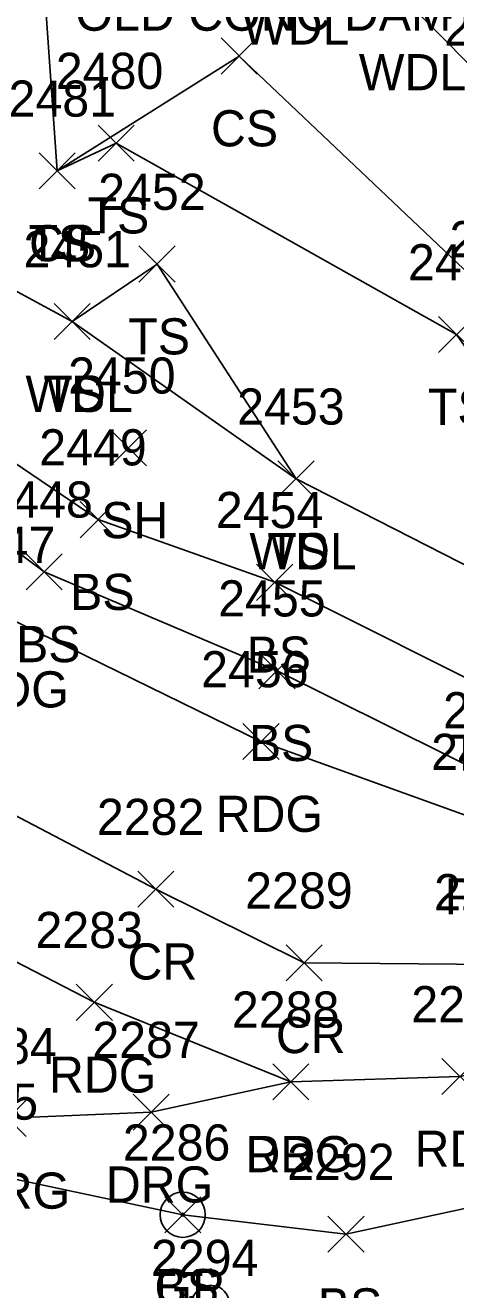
# Model space of a CAD drawing. Extents: x 1512665 to 1513714, y 110636 to 112816.
# Drawn here: x 1512998.3 to 1513022.1, y 110740.2 to 110810.2 of the extents above; entities that cross this region are included whole.
import ezdxf

# ---------------------------------------------------------------- set-up
doc = ezdxf.new("R2010")
doc.units = 0
for name, color, linetype in [('C_C', 7, 'Continuous'), ('L_A', 7, 'Continuous'), ('L_C', 7, 'Continuous'), ('L_I', 7, 'Continuous'), ('L_TIC', 7, 'Continuous'), ('LAWA', 7, 'Continuous'), ('LELB', 7, 'Continuous'), ('LTD', 7, 'Continuous'), ('P_A', 7, 'Continuous'), ('P_I', 7, 'Continuous'), ('P_TIC', 7, 'Continuous'), ('PEU', 7, 'Continuous'), ('PRC', 7, 'Continuous'), ('R_A', 7, 'Continuous'), ('R_I', 7, 'Continuous'), ('R_TIC', 7, 'Continuous'), ('RDG', 7, 'Continuous'), ('RGP', 7, 'Continuous')]:
    doc.layers.add(name, color=color, linetype=linetype)

msp = doc.modelspace()

# ---------------------------------------------------------------- linework, layer by layer
at = {"layer": 'L_TIC'}
for points in [[(1513009.115, 110807.489), (1513011.115, 110809.489)], [(1513011.115, 110807.489), (1513009.115, 110809.489)], [(1513002.312, 110802.67), (1513004.312, 110804.67)], [(1513004.312, 110802.67), (1513002.312, 110804.67)], [(1512999.042, 110801.133), (1513001.042, 110803.133)], [(1513001.042, 110801.133), (1512999.042, 110803.133)], [(1512999.042, 110801.133), (1513001.042, 110803.133)], [(1513001.042, 110801.133), (1512999.042, 110803.133)], [(1513004.569, 110795.978), (1513006.569, 110797.978)], [(1513006.569, 110795.978), (1513004.569, 110797.978)], [(1512999.869, 110792.798), (1513001.869, 110794.798)], [(1513001.869, 110792.798), (1512999.869, 110794.798)], [(1512999.869, 110792.798), (1513001.869, 110794.798)], [(1513001.869, 110792.798), (1512999.869, 110794.798)], [(1513021.152, 110792.076), (1513023.152, 110794.076)], [(1513023.152, 110792.076), (1513021.152, 110794.076)], [(1513002.992, 110785.812), (1513004.992, 110787.812)], [(1513004.992, 110785.812), (1513002.992, 110787.812)], [(1513012.264, 110784.095), (1513014.264, 110786.095)], [(1513014.264, 110784.095), (1513012.264, 110786.095)], [(1513012.264, 110784.095), (1513014.264, 110786.095)], [(1513014.264, 110784.095), (1513012.264, 110786.095)], [(1513001.316, 110781.838), (1513003.316, 110783.838)], [(1513003.316, 110781.838), (1513001.316, 110783.838)], [(1512998.323, 110778.951), (1513000.323, 110780.951)], [(1513000.323, 110778.951), (1512998.323, 110780.951)], [(1513011.084, 110778.37), (1513013.084, 110780.37)], [(1513013.084, 110778.37), (1513011.084, 110780.37)], [(1513011.212, 110773.48), (1513013.212, 110775.48)], [(1513013.212, 110773.48), (1513011.212, 110775.48)], [(1513005.992, 110743.376), (1513007.992, 110745.376)], [(1513007.992, 110743.376), (1513005.992, 110745.376)], [(1513015.029, 110742.308), (1513017.029, 110744.308)], [(1513017.029, 110742.308), (1513015.029, 110744.308)]]:
    msp.add_lwpolyline(points, dxfattribs=at)
at = {"layer": 'LAWA'}
msp.add_lwpolyline([(1512988.199, 110800.659), (1513000.869, 110793.798), (1513013.264, 110785.095), (1513028.637, 110777.265), (1513031.778, 110776.166), (1513035.849, 110774.486), (1513038.334, 110774.274), (1513040.786, 110775.756), (1513040.029, 110778.791), (1513034.839, 110783.794), (1513031.373, 110791.45), (1513032.455, 110794.874), (1513030.687, 110802.22), (1513024.783, 110806.061), (1513019.321, 110811.594), (1513012.859, 110814.122), (1513012.233, 110818.887), (1513011.96, 110820.134), (1513029.824, 110821.619), (1513035.802, 110824.023), (1513038.307, 110832.035), (1513040.001, 110853.344)], dxfattribs=at)
at = {"layer": 'LELB'}
for points in [[(1513042.977, 110772.935), (1513038.334, 110774.274), (1513035.486, 110779.791), (1513033.224, 110783.595), (1513025.018, 110794.357), (1513010.115, 110808.489), (1513000.042, 110802.133), (1512999.104, 110815.556), (1513001.845, 110823.582), (1513003.953, 110835.587)], [(1512965.768, 110809.049), (1512985.021, 110794.556), (1513002.316, 110782.838), (1513012.084, 110779.37), (1513025.948, 110772.452), (1513031.778, 110776.166)], [(1512964.105, 110806.986), (1512983.29, 110791.889), (1512999.323, 110779.951), (1513012.212, 110774.48), (1513024.663, 110768.294), (1513032.242, 110771.906), (1513035.849, 110774.486)], [(1513035.486, 110779.791), (1513029.907, 110781.961), (1513022.152, 110793.076), (1513003.312, 110803.67), (1513000.042, 110802.133)], [(1513000.869, 110793.798), (1513005.569, 110796.978), (1513013.264, 110785.095)], [(1512958.132, 110793.433), (1512973.652, 110777.453), (1512981.607, 110755.641), (1512996.294, 110746.637), (1513006.992, 110744.376), (1513016.029, 110743.308), (1513026.953, 110745.673), (1513036.177, 110748.289)]]:
    msp.add_lwpolyline(points, dxfattribs=at)
at = {"layer": 'LTD'}
msp.add_arc((1513008.539, 110739.425), 1.047, 335.52715, 180.95627, dxfattribs=at)
at = {"layer": 'P_TIC'}
for points in [[(1513010.324, 110769.561), (1513012.324, 110771.561)], [(1513012.324, 110769.561), (1513010.324, 110771.561)], [(1513004.499, 110761.392), (1513006.499, 110763.392)], [(1513006.499, 110761.392), (1513004.499, 110763.392)], [(1513012.716, 110757.318), (1513014.716, 110759.318)], [(1513014.716, 110757.318), (1513012.716, 110759.318)], [(1513001.098, 110755.133), (1513003.098, 110757.133)], [(1513003.098, 110755.133), (1513001.098, 110757.133)], [(1513011.974, 110750.731), (1513013.974, 110752.731)], [(1513013.974, 110750.731), (1513011.974, 110752.731)], [(1513021.336, 110751.03), (1513023.336, 110753.03)], [(1513023.336, 110751.03), (1513021.336, 110753.03)]]:
    msp.add_lwpolyline(points, dxfattribs=at)
at = {"layer": 'PEU'}
for points in [[(1512701.918, 111049.687), (1512700.272, 111027.695), (1512701.575, 110993.777), (1512707.634, 110973.739), (1512708.973, 110956.468), (1512713.567, 110946.899), (1512719.219, 110936.541), (1512726.895, 110929.376), (1512741.614, 110919.596), (1512758.159, 110912.379), (1512787.354, 110896.005), (1512813.053, 110887.984), (1512838.367, 110874.777), (1512855.917, 110864.835), (1512882.817, 110848.349), (1512898.24, 110841.366), (1512913.486, 110833.402), (1512927.92, 110827.382), (1512944.462, 110817.212), (1512962.879, 110803.833), (1512982.126, 110789.052), (1512997.253, 110777.445), (1513011.324, 110770.561), (1513024.004, 110765.991)], [(1512908.545, 110823.763), (1512922.462, 110816.848), (1512937.29, 110809.107), (1512956.028, 110794.571), (1512958.132, 110793.433), (1512975.798, 110779.469), (1512988.794, 110763.009), (1513002.098, 110756.133), (1513012.974, 110751.731), (1513022.336, 110752.03), (1513042.715, 110756.056), (1513045.977, 110758.546), (1513043.773, 110764.486), (1513041.72, 110768.766), (1513036.521, 110767.718), (1513024.004, 110765.991)]]:
    msp.add_lwpolyline(points, dxfattribs=at)
at = {"layer": 'PRC'}
msp.add_lwpolyline([(1512910.919, 110828.697), (1512924.695, 110822.052), (1512939.408, 110813.161), (1512959.787, 110799.435), (1512979.162, 110782.894), (1512994.968, 110767.907), (1513005.499, 110762.392), (1513013.716, 110758.318), (1513024.25, 110758.228), (1513034.128, 110760.688), (1513043.773, 110764.486)], dxfattribs=at)
at = {"layer": 'R_TIC'}
for points in [[(1513011.974, 110750.731), (1513013.974, 110752.731)], [(1513013.974, 110750.731), (1513011.974, 110752.731)], [(1513004.245, 110749.054), (1513006.245, 110751.054)], [(1513006.245, 110749.054), (1513004.245, 110751.054)], [(1512996.328, 110748.713), (1512998.328, 110750.713)], [(1512998.328, 110748.713), (1512996.328, 110750.713)]]:
    msp.add_lwpolyline(points, dxfattribs=at)
at = {"layer": 'RDG'}
msp.add_lwpolyline([(1512988.794, 110763.009), (1512997.328, 110749.713), (1513005.245, 110750.054), (1513012.974, 110751.731)], dxfattribs=at)
at = {"layer": 'RGP'}
msp.add_line((1513006.992, 110744.376), (1513006.992, 110744.376), dxfattribs=at)
for radius in [1.25, 0.0833]:
    msp.add_circle((1513006.992, 110744.376), radius, dxfattribs=at)

# ---------------------------------------------------------------- texts
at = {"layer": 'C_C'}
msp.add_text('TIE=25.02', height=2, dxfattribs=at).set_placement((1513021.817, 110768.939))
at = {"layer": 'L_A'}
for s, p in [('WDL', (1513010.276, 110809.122)), ('WDL', (1513016.738, 110806.594)), ('CS', (1513008.556, 110803.489)), ('TS', (1513001.721, 110798.67)), ('TS', (1512998.452, 110797.133)), ('CS', (1512998.483, 110797.133)), ('TS', (1513003.979, 110791.978)), ('TS', (1512999.278, 110788.798)), ('WDL', (1512998.286, 110788.798)), ('TS', (1513020.561, 110788.076)), ('SH', (1513002.48, 110781.812)), ('WDL', (1513010.681, 110780.095)), ('TS', (1513011.673, 110780.095)), ('BS', (1513000.757, 110777.838)), ('BS', (1512997.764, 110774.951)), ('BS', (1513010.525, 110774.37)), ('BS', (1513010.653, 110769.48)), ('BS', (1513005.433, 110739.376)), ('BS', (1513014.47, 110738.308))]:
    msp.add_text(s, height=2, dxfattribs=at).set_placement(p)
at = {"layer": 'L_C'}
msp.add_text('OLD CONC DAM', height=2, dxfattribs=at).set_placement((1513001.052, 110809.887))
at = {"layer": 'L_I'}
for s, p in [('2476', (1513021.469, 110809.061)), ('2480', (1512999.965, 110806.67)), ('2481', (1512997.35, 110805.133)), ('2481', (1512997.35, 110805.133)), ('2452', (1513002.309, 110799.978)), ('2472', (1513021.758, 110797.357)), ('2451', (1512998.176, 110796.798)), ('2451', (1512998.176, 110796.798)), ('2471', (1513019.459, 110796.076)), ('2450', (1513000.645, 110789.812)), ('2453', (1513010.004, 110788.095)), ('2453', (1513010.004, 110788.095)), ('2449', (1512999.048, 110785.838)), ('2448', (1512996.064, 110782.951)), ('2454', (1513008.825, 110782.37)), ('2455', (1513008.952, 110777.48)), ('2458', (1513021.403, 110771.294)), ('2285', (1512993.034, 110749.637)), ('2286', (1513003.677, 110747.376)), ('2292', (1513012.769, 110746.308)), ('2294', (1513005.232, 110740.991))]:
    msp.add_text(s, height=2, dxfattribs=at).set_placement(p)
at = {"layer": 'P_A'}
for s, p in [('RDG', (1512994.742, 110772.445)), ('RDG', (1513008.813, 110765.561)), ('RDG', (1513021.492, 110760.991)), ('RDG', (1513021.492, 110760.991)), ('CR', (1513003.932, 110757.392)), ('CR', (1513012.149, 110753.318)), ('RDG', (1512999.586, 110751.133)), ('RDG', (1513019.825, 110747.03)), ('RDG', (1513010.462, 110746.731))]:
    msp.add_text(s, height=2, dxfattribs=at).set_placement(p)
at = {"layer": 'P_I'}
for s, p in [('2447', (1512993.994, 110780.445)), ('2456', (1513008.01, 110773.561)), ('2457', (1513020.744, 110768.991)), ('2457', (1513020.744, 110768.991)), ('2282', (1513002.239, 110765.392)), ('2289', (1513010.448, 110761.318)), ('2290', (1513020.904, 110761.228)), ('2283', (1512998.838, 110759.133)), ('2288', (1513009.714, 110754.731)), ('2291', (1513019.643, 110755.03))]:
    msp.add_text(s, height=2, dxfattribs=at).set_placement(p)
at = {"layer": 'R_A'}
for s, p in [('DRG', (1513010.462, 110746.731)), ('DRG', (1512994.816, 110744.713)), ('DRG', (1513002.734, 110745.054)), ('GP', (1513005.425, 110739.376))]:
    msp.add_text(s, height=2, dxfattribs=at).set_placement(p)
at = {"layer": 'R_I'}
for s, p in [('2288', (1513009.714, 110754.731)), ('2284', (1512994.068, 110752.713)), ('2287', (1513001.986, 110753.054)), ('2286', (1513003.677, 110747.376))]:
    msp.add_text(s, height=2, dxfattribs=at).set_placement(p)

doc.saveas('drawing.dxf')
